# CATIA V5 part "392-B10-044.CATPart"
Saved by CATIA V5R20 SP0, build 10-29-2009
Part number: 392-B10-044
Definition: NONE
Nomenclature: 392-B10-044
Source: Unknown
Description: 392-B10-044
Bounding box of the stored display mesh (mm): x 0 to 44, y -4.695 to 4.695, z -4.65 to 4.65
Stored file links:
  C:\Users\Utente\Desktop\IO LAVORO\3D X SITO CF\X SITO\3D files 392B\392-B10-044.CATPart
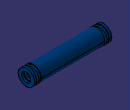
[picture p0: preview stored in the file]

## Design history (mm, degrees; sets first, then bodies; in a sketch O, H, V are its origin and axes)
Body1 "392-B10-044" (main body)
  Solid1: solid without history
